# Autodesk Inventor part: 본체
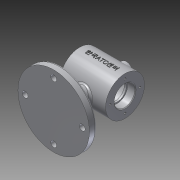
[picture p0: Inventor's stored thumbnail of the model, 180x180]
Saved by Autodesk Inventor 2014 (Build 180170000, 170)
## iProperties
Created: 2018-12
Part Number: 본체
Material: 알루미늄 6061
Document SubType Name: Modeling
Designer: 601-22
Density: 2.71 g/cm^3
Appearance: 알루미늄 - 평지
Author: 601-22
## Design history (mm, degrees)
sketch "스케치1"
  geometry: L1 (0, 0)-(70, 0); L2 (0, 0)-(70, 0); L3 (70, 0)-(70, 30); L4 (70, 30)-(0, 30); L5 (0, 30)-(0, 0)
  constraints: 10 end point, 2 horizontal, 2 parallel, 1 perpendicular
  dimensions: "d0" = 70 distance of L1.start L1.end; "d1" = 30 distance between parallel lines of L2 L4
revolve "회전1" sketch "스케치1" stored, may be unused: angle "d2" = 90 deg
sketch "스케치2"
  geometry: L1 (0, -30)-(0, 30) reference; L2 (70, -30)-(70, 30) reference; L3 (0, 0)-(70, 0); L4 (0, 0)-(12, 0); L5 (12, 0)-(12, 16); L6 (12, 16)-(0, 16); L7 (0, 16)-(0, 0); L8 (12, 0)-(15, 0); L9 (15, 0)-(15, 14); L10 (15, 14)-(12, 14); L11 (12, 14)-(12, 0); L12 (15, 0)-(55, 0); L13 (55, 0)-(55, 22); L14 (52, 25)-(18, 25); L15 (15, 22)-(15, 0); L16 (55, 0)-(58, 0); L17 (58, 0)-(58, 14); L18 (58, 14)-(55, 14); L19 (55, 14)-(55, 0); L20 (58, 0)-(70, 0); L21 (70, 0)-(70, 16); L22 (70, 16)-(58, 16); L23 (58, 16)-(58, 0); A1 r 3 centre (18, 22) between (18, 25) and (15, 22); A2 r 3 centre (52, 22) between (55, 22) and (52, 25); 2 further points
  constraints: 42 end point, 10 parallel, 6 perpendicular, 5 horizontal, 4 point on circle, 4 point on line, 4 tangent, 2 centre point, 1 midpoint
  dimensions: "d3" = 12 distance of L6.end L5.end; "d4" = 3 distance of L10.end L9.end; "d5" = 40 distance of point (15, 25) point (55, 25); "d6" = 3 distance of L18.end L17.end; "d7" = 12 distance of L22.end L21.end; "d8" = 16 distance between parallel lines of L3 L6; "d9" = 14 distance between parallel lines of L3 L10; "d10" = 25 distance between parallel lines of L12 L14; "d11" = 14 distance between parallel lines of L16 L18; "d12" = 16 distance between parallel lines of L20 L22; "d13" = 3 radius of A1; "d14" = 3 radius of A2
revolve "회전2" sketch "스케치2" stored, may be unused: angle "d15" = 90 deg
node "작업 평면3"
sketch "스케치5"
  geometry: L1 (0, 30)-(0, -30) reference; L2 (-70, 30)-(-70, -30) reference; L3 (0, -30)-(-70, -30) reference; L4 (0, 30)-(-70, 30) reference; L5 (0, 0)-(-70, 0); L6 (-35, -30)-(-35, 30); C1 r 55 at (-35, 0)
  constraints: 4 end point, 4 midpoint, 1 centre point
  dimensions: "d25" = 110 diameter of C1
extrude "돌출1" join sketch "스케치5" distance "d26" = 11; taper "d27" = 0 deg
sketch "스케치6"
  geometry: L1 (90, -64)-(-20, -64) reference; L2 (0, -30)-(70, -30) reference; L3 (35, -27.651)-(35, -64); L4 (-20, -64)-(23, -52.478); L5 (23, -52.478)-(23, -27.651); L6 (23, -27.651)-(35, -27.651); L7 (-20, -64)-(35, -64); 1 further point
  constraints: 10 end point, 2 perpendicular, 1 collinear, 1 midpoint, 1 parallel
  dimensions: "d28" = 15 deg angle of L1 L4; "d29" = 12 distance between parallel lines of L5 L3; "d30" = 55 distance from line of L1.end L3
revolve "회전3" sketch "스케치6" stored, may be unused: angle "d31" = 90 deg
node "작업 평면4"
sketch "스케치7"
  geometry: L1 (-32.072, 11.637)-(-37.928, 11.637) reference; L2 (-37.928, -11.637)-(-32.072, -11.637) reference; L3 (0, 30)-(0, -30) reference; L4 (-70, 30)-(-70, -30) reference; L5 (0, 0)-(-70, 0); L6 (-35, 0)-(-35, -23.091); C1 r 10 at (-35, 0)
  constraints: 4 end point, 2 midpoint, 2 vertical alignment, 1 centre point, 1 coincident, 1 perpendicular
  dimensions: "d33" = 20 diameter of C1
extrude "돌출2" join sketch "스케치7" stored distance "d34" = 11; taper "d35" = 0 deg
sketch "스케치8"
  geometry: C1 r 10 at (0, 0) reference; C2 r 5 at (0, 0); 1 further point
  constraints: 1 centre point, 1 coincident
  dimensions: "d36" = 10 diameter of C2
extrude "돌출3" cut sketch "스케치8" distance "d37" = 25; taper "d38" = 0 deg
chamfer "모따기1" distance "d39" = 1; stored, may be unused: second distance "d40" = 2, angle "d41" = 45 deg
fillet "모깎기1" dims "d42" = 3
sketch "스케치10" dims "d43" = 46
  geometry: L1 (0, 0)-(0, 27.65); C1 r 17 at (0, 0) reference; 1 further point
  constraints: 2 end point, 1 coincident, 1 point on line, 1 vertical, 1 vertical alignment, 2 other
hole "구멍1" sketch "스케치10" at (0, 23) diameter "d44" = 3.242; stored, may be unused: countersink angle "d48" = 90 deg, drill point angle "d50" = 118 deg; dims "d45" = 8, "d46" = 4, "d47" = 2, "d49" = 10
node "작업 평면5"
node "작업 평면7"
node "작업 평면8"
sketch "스케치13" dims "d67" = 88
  geometry: L1 (-35, 0)-(-35, 48.388); C1 r 55 at (-35, 0) reference; 2 further points
  constraints: 2 end point, 1 coincident, 1 point on line, 1 vertical, 1 vertical alignment, 2 other
hole "구멍3" sketch "스케치13" at (-35, 44) diameter "d68" = 9; stored, may be unused: countersink angle "d72" = 90 deg, drill point angle "d74" = 0 deg; dims "d69" = 8, "d70" = 14, "d71" = 10, "d73" = 20
node "작업 평면9"
sketch "스케치14"
  geometry: L1 (0, 30)-(70, 30) reference; L2 (35, 30)-(35, -18.358); L3 (10.368, 3.602)-(59.632, 3.602); L4 (59.632, 3.602)-(59.632, -3.602); L5 (59.632, -3.602)-(10.368, -3.602); L6 (10.368, -3.602)-(10.368, 3.602); 3 further points
  constraints: 3 midpoint, 2 end point, 1 perpendicular, 2 other
  dimensions: "d79" = 30 distance from line of point (59.632, 0) L1; "d80" = 0 distance from line of L2 point (35, 3.602)
feature "엠보싱1" sketch "스케치14" dims "d1" = 30, "d81" = 0.5, "d82" = 0
node "솔리드1"
pattern_circular "원형 패턴1" dims angle "d52" = 360 deg
mirror "대칭1"
pattern_circular "원형 패턴2" dims angle "d76" = 360 deg
node "투영된 루프1"
node "투영된 루프2"
node "투영된 루프3"
other parameters: "d24" = -75, "d32" = 37, "d54" = 35, "d66" = -55
